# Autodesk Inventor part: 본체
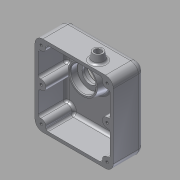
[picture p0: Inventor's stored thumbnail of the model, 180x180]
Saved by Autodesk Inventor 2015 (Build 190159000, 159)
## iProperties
Created: 2015-10
Part Number: 본체
Material: 알루미늄 6061
Document SubType Name: Modeling
Designer: mduedu
Density: 1 g/cm^3
Appearance: 알루미늄 - 평지
Author: mduedu
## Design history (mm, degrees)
sketch "스케치1"
  geometry: L1 (-50, -51.5)-(50, -51.5); L2 (50, -51.5)-(50, 51.5); L3 (50, 51.5)-(-50, 51.5); L4 (-50, 51.5)-(-50, -51.5); L5 (-50, -51.5)-(50, 51.5); L6 (50, -51.5)-(-50, 51.5); 1 further point
  constraints: 12 end point, 2 midpoint, 2 parallel, 1 horizontal, 1 perpendicular
  dimensions: "d0" = 100 distance of L3.end L2.end; "d1" = 103 distance of L2.end L1.end
extrude "돌출1" new body sketch "스케치1" distance "d2" = 40; taper "d3" = 0 deg
fillet "모깎기1" dims "d4" = 10
fillet "모깎기2" dims "d5" = 8
feature "쉘1" dims "d6" = 4
sketch "스케치2"
  geometry: L1 (-50, 41.5)-(-50, -41.5) reference; L2 (50, -41.5)-(50, 41.5) reference; L3 (-50, 0)-(50, 0); L4 (40, 51.5)-(-40, 51.5) reference; L5 (-40, -51.5)-(40, -51.5) reference; L6 (0, 51.5)-(0, -51.5); C1 r 6 at (-42, 43.5); C2 r 6 at (-42, 0); C3 r 6 at (-42, -43.5); C4 r 6 at (42, 43.5); C5 r 6 at (42, 0); C6 r 6 at (42, -43.5); 1 further point
  constraints: 6 centre point, 4 end point, 4 midpoint, 4 symmetric about line, 1 point on line, 1 vertical alignment, 4 other
  dimensions: "d7" = 12 diameter of C1; "d10" = 12 diameter of C2 (= d7); "d16" = 8 distance from line of C1.centre L1; "d17" = 8 distance from line of C1.centre L4
extrude "돌출2" join sketch "스케치2" stored distance "d11" = 0; taper "d12" = 0 deg
fillet "모깎기3" dims "d13" = 3
sketch "스케치3"
  geometry: A1 r 6 centre (-42, 43.5) between (-42.667, 37.537) and (-36.037, 44.167) reference; A2 r 6 centre (42, 43.5) between (36.037, 44.167) and (42.667, 37.537) reference; A3 r 6 centre (42, 0) between (42.667, 5.963) and (42.667, -5.963) reference; A4 r 6 centre (-42, 0) between (-42.667, -5.963) and (-42.667, 5.963) reference; A5 r 6 centre (-42, -43.5) between (-36.037, -44.167) and (-42.667, -37.537) reference; A6 r 6 centre (42, -43.5) between (42.667, -37.537) and (36.037, -44.167) reference; 7 further points
  constraints: 6 coincident
hole "구멍1" sketch "스케치3" at (-42, 43.5), (-42, 0), (-42, -43.5), (42, -43.5), (42, 0), (42, 43.5) diameter "d18" = 3.242; stored, may be unused: countersink angle "d22" = 90 deg, drill point angle "d24" = 118 deg; dims "d19" = 12, "d20" = 4, "d21" = 2, "d23" = 14
sketch "스케치4"
  geometry: L1 (90, 0)-(80, 0) reference; L2 (90, 0)-(90, 32) reference; C1 r 8 at (58.594, 12); 1 further point
  constraints: 1 centre point
  dimensions: "d25" = 16 diameter of C1; "d26" = 12 distance from line of L1 C1.centre; "d27" = 31.406 distance from line of C1.centre L2
extrude "돌출3" join sketch "스케치4" distance "d28" = 10; taper "d29" = -10 deg
sketch "스케치5"
  geometry: C1 r 8 at (0, 0) reference; C2 r 4 at (0, 0); 1 further point
  constraints: 1 centre point, 1 coincident
  dimensions: "d30" = 8 diameter of C2
extrude "돌출4" cut sketch "스케치5" stored distance "d31" = 0; taper "d32" = 0 deg
chamfer "모따기1" distance "d33" = 0.5; stored, may be unused: second distance "d34" = 2, angle "d35" = 45 deg
fillet "모깎기4" dims "d36" = 3
sketch "스케치6"
  geometry: L1 (73, 8)-(-7, 8) reference; L2 (-17, -2)-(-17, -85) reference; C1 r 21.5 at (23, -32); 1 further point
  constraints: 1 centre point
  dimensions: "d37" = 43 diameter of C1; "d38" = 40 distance from line of C1.centre L1; "d39" = 40 distance from line of C1.centre L2
extrude "돌출5" join sketch "스케치6" distance "d40" = 15; taper "d41" = -10 deg
hole "구멍2" diameter "d44" = 25; stored, may be unused: countersink angle "d48" = 90 deg, drill point angle "d50" = 0 deg; dims "d42" = 10, "d43" = 10, "d45" = 10, "d46" = 4, "d47" = 2, "d49" = 7
hole "구멍3" diameter "d53" = 20; stored, may be unused: countersink angle "d57" = 90 deg, drill point angle "d59" = 0 deg; dims "d51" = 10, "d52" = 10, "d54" = 10, "d55" = 32, "d56" = 9, "d58" = 7
chamfer "모따기2" distance "d60" = 1; stored, may be unused: second distance "d61" = 2, angle "d62" = 45 deg
sketch "스케치7"
  geometry: L1 (-50, 41.5)-(-50, -41.5) reference; L2 (-40, -51.5)-(40, -51.5) reference; 2 further points
  constraints: 1 other
  dimensions: "d63" = 50 distance from line of point (0, -21.5) L1; "d64" = 30 distance from line of point (0, -21.5) L2
feature "엠보싱1" sketch "스케치7" dims "d0" = 100, "d1" = 103, "d65" = 0.5, "d66" = 0
fillet "모깎기5" dims "d67" = 3
fillet "모깎기6" dims "d68" = 0.3
chamfer "모따기3" distance "d69" = 0.5; stored, may be unused: second distance "d70" = 2, angle "d71" = 45 deg
node "솔리드1"
